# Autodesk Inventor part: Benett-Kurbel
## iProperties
Created: 2004-09
Part Number: Benett-Kurbel
Document SubType Name: Modeling
Designer: W. Holzwarth
Manufacturer: Standard
Standards Organization: Custom
Author: W. Holzwarth
